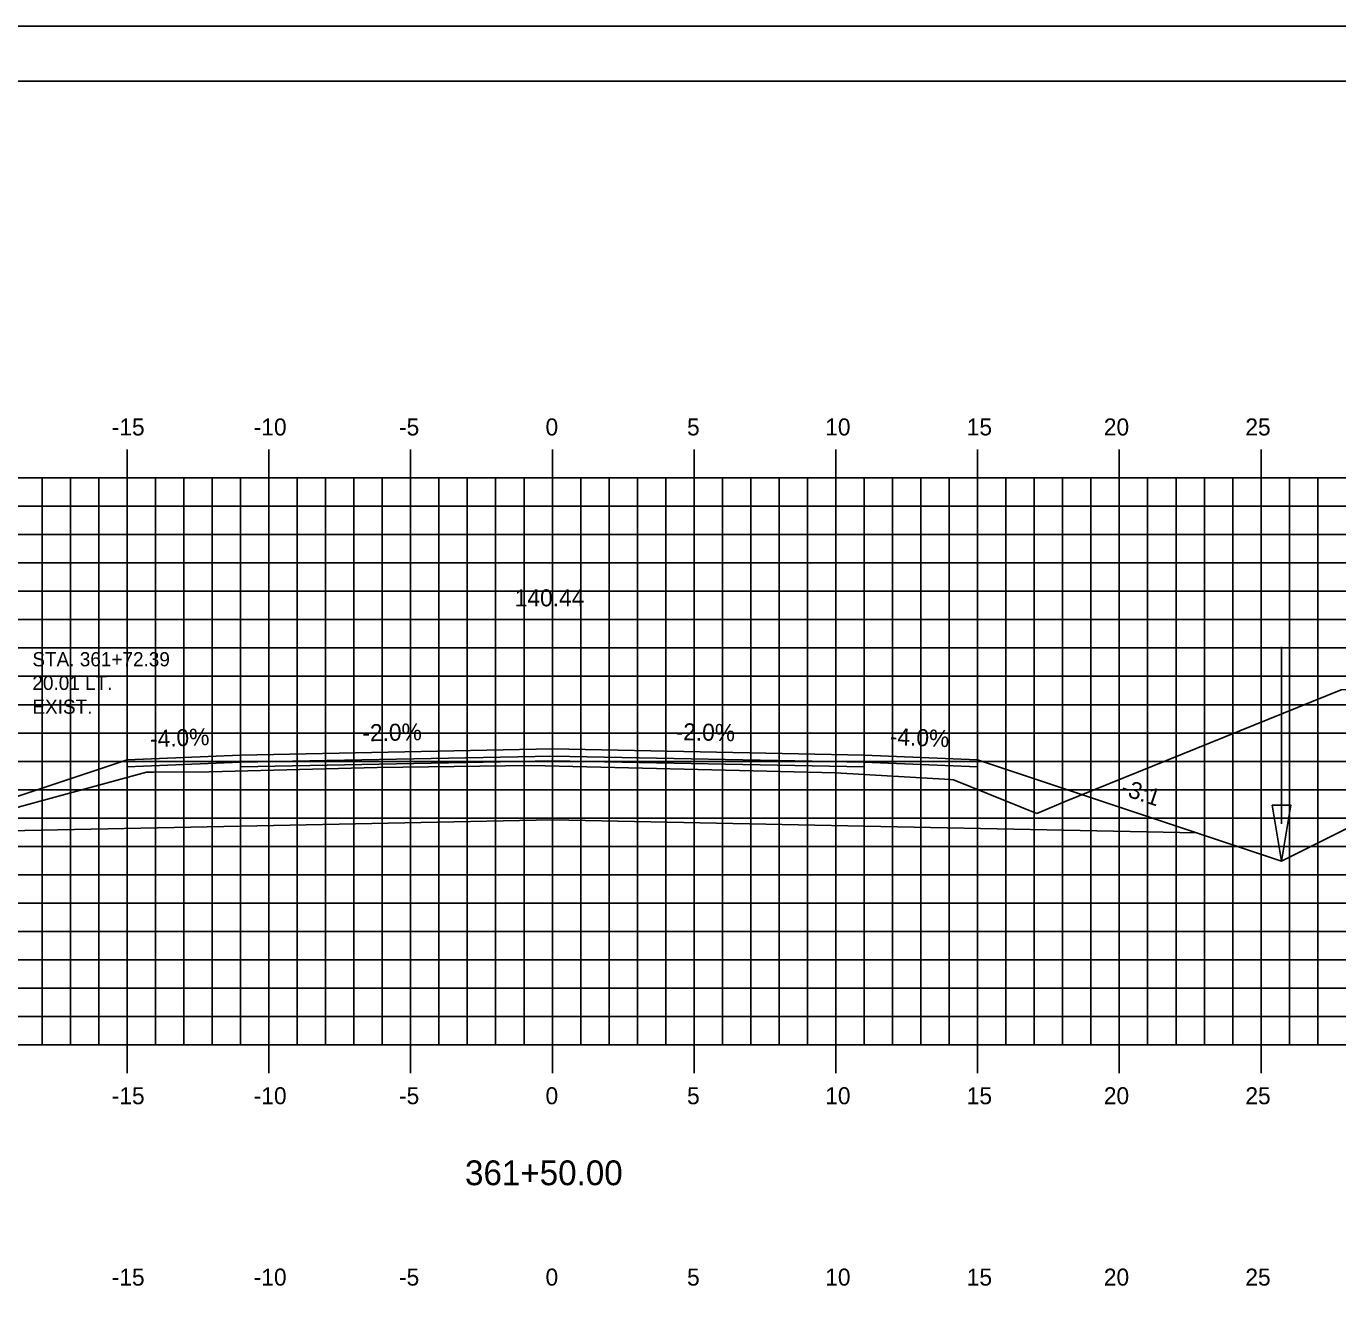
# Model space of a CAD drawing. Extents: x 1146525 to 1146695, y 608981 to 609091.
# Drawn here: x 1146589.11 to 1146635.38, y 609046.58 to 609091.28 of the extents above; entities that cross this region are included whole.
import ezdxf

# ---------------------------------------------------------------- set-up
doc = ezdxf.new("R2010")
doc.units = 0
for name, color, linetype in [('ANNOTATION', 7, 'Continuous'), ('BORDER', 7, 'Continuous'), ('D_Drainage_Ditch_Line', 7, 'Continuous'), ('D_Roadway_Centerline', 7, 'Continuous'), ('D_Roadway_Centerline_Text', 7, 'Continuous'), ('D_Roadway_Edge_Shoulder', 7, 'Continuous'), ('D_Roadway_Edge_TW', 7, 'Continuous'), ('D_Roadway_Pavement', 7, 'Continuous'), ('D_Roadway_SlopeLines', 7, 'Continuous'), ('D_Roadway_SubGrade', 7, 'Continuous'), ('D_Text_Monospaced', 7, 'Continuous'), ('H_V ANNOTATION', 7, 'Continuous'), ('MAJOR', 7, 'Continuous'), ('MINOR', 7, 'Continuous'), ('PLOT BOUNDARY', 7, 'Continuous'), ('S_Roadway_Centerline', 7, 'Continuous')]:
    doc.layers.add(name, color=color, linetype=linetype)

msp = doc.modelspace()

# ---------------------------------------------------------------- linework, layer by layer
msp.add_lwpolyline([(1146572.045, 609065.661), (1146573.295, 609065.521), (1146574.545, 609065.242), (1146575.795, 609064.824), (1146577.045, 609064.269), (1146581.947, 609061.818), (1146584.947, 609062.818), (1146592.67, 609065.392), (1146592.671, 609065.392), (1146596.671, 609065.552), (1146607.671, 609065.772), (1146618.671, 609065.552), (1146622.671, 609065.392), (1146630.395, 609062.818), (1146633.395, 609061.818), (1146643.18, 609066.71), (1146644.43, 609067.259), (1146645.68, 609067.654), (1146646.93, 609067.897), (1146648.18, 609067.986)])
at = {"layer": 'BORDER'}
msp.add_lwpolyline([(1146532.671, 608984.335), (1146692.671, 608984.335), (1146692.671, 609089.335), (1146532.671, 609089.335)], close=True, dxfattribs=at)
at = {"layer": 'D_Drainage_Ditch_Line'}
msp.add_line((1146633.395, 609063.13), (1146633.395, 609069.374), dxfattribs=at)
msp.add_lwpolyline([(1146633.067, 609063.786), (1146633.723, 609063.786), (1146633.395, 609061.818)], close=True, dxfattribs=at)
at = {"layer": 'D_Roadway_Edge_Shoulder'}
for points in [[(1146596.671, 609065.552), (1146592.671, 609065.392), (1146592.671, 609065.142), (1146596.671, 609065.302)], [(1146618.671, 609065.552), (1146622.671, 609065.392), (1146622.671, 609065.142), (1146618.671, 609065.302)]]:
    msp.add_lwpolyline(points, close=True, dxfattribs=at)
at = {"layer": 'D_Roadway_Edge_TW'}
msp.add_lwpolyline([(1146596.671, 609065.302), (1146596.671, 609065.552), (1146607.671, 609065.772), (1146618.671, 609065.552), (1146618.671, 609065.302), (1146607.671, 609065.522)], close=True, dxfattribs=at)
at = {"layer": 'D_Roadway_Pavement'}
msp.add_lwpolyline([(1146596.671, 609065.136), (1146596.671, 609065.302), (1146607.671, 609065.522), (1146618.671, 609065.302), (1146618.671, 609065.136), (1146607.671, 609065.356)], close=True, dxfattribs=at)
at = {"layer": 'D_Roadway_SlopeLines'}
for points in [[(1146633.395, 609061.818), (1146643.18, 609066.71), (1146644.43, 609067.259), (1146645.68, 609067.654), (1146646.93, 609067.897), (1146648.18, 609067.986)], [(1146630.395, 609062.818), (1146633.395, 609061.818)]]:
    msp.add_lwpolyline(points, dxfattribs=at)
at = {"layer": 'D_Roadway_SubGrade'}
for points in [[(1146596.671, 609065.136), (1146596.671, 609065.302), (1146592.671, 609065.142), (1146592.671, 609065.392), (1146592.67, 609065.392), (1146584.947, 609062.818), (1146596.671, 609063.052)], [(1146596.671, 609063.052), (1146596.671, 609065.136), (1146607.671, 609065.356), (1146618.671, 609065.136), (1146618.671, 609063.052), (1146607.671, 609063.272)], [(1146618.671, 609065.136), (1146618.671, 609065.302), (1146622.671, 609065.142), (1146622.671, 609065.392), (1146622.671, 609065.392), (1146630.395, 609062.818), (1146618.671, 609063.052)]]:
    msp.add_lwpolyline(points, close=True, dxfattribs=at)
at = {"layer": 'MAJOR'}
for p, q in [((1146592.671, 609076.337), (1146592.671, 609075.335)), ((1146597.671, 609076.337), (1146597.671, 609075.335)), ((1146602.671, 609076.337), (1146602.671, 609075.335)), ((1146607.671, 609076.337), (1146607.671, 609075.335)), ((1146612.671, 609076.337), (1146612.671, 609075.335)), ((1146617.671, 609076.337), (1146617.671, 609075.335)), ((1146622.671, 609076.337), (1146622.671, 609075.335)), ((1146627.671, 609076.337), (1146627.671, 609075.335)), ((1146632.671, 609076.337), (1146632.671, 609075.335)), ((1146537.671, 609075.335), (1146677.671, 609075.335)), ((1146537.671, 609075.335), (1146677.671, 609075.335)), ((1146592.671, 609055.335), (1146592.671, 609075.335)), ((1146597.671, 609055.335), (1146597.671, 609075.335)), ((1146602.671, 609055.335), (1146602.671, 609075.335)), ((1146607.671, 609055.335), (1146607.671, 609075.335)), ((1146612.671, 609055.335), (1146612.671, 609075.335)), ((1146617.671, 609055.335), (1146617.671, 609075.335)), ((1146622.671, 609055.335), (1146622.671, 609075.335)), ((1146627.671, 609055.335), (1146627.671, 609075.335)), ((1146632.671, 609055.335), (1146632.671, 609075.335)), ((1146537.671, 609070.335), (1146677.671, 609070.335)), ((1146537.671, 609065.335), (1146677.671, 609065.335)), ((1146537.671, 609060.335), (1146677.671, 609060.335)), ((1146537.671, 609055.335), (1146677.671, 609055.335)), ((1146537.671, 609055.335), (1146677.671, 609055.335)), ((1146592.671, 609054.333), (1146592.671, 609055.335)), ((1146597.671, 609054.333), (1146597.671, 609055.335)), ((1146602.671, 609054.333), (1146602.671, 609055.335)), ((1146607.671, 609054.333), (1146607.671, 609055.335)), ((1146612.671, 609054.333), (1146612.671, 609055.335)), ((1146617.671, 609054.333), (1146617.671, 609055.335)), ((1146622.671, 609054.333), (1146622.671, 609055.335)), ((1146627.671, 609054.333), (1146627.671, 609055.335)), ((1146632.671, 609054.333), (1146632.671, 609055.335))]:
    msp.add_line(p, q, dxfattribs=at)
at = {"layer": 'MINOR'}
for p, q in [((1146589.671, 609055.335), (1146589.671, 609075.335)), ((1146590.671, 609055.335), (1146590.671, 609075.335)), ((1146591.671, 609055.335), (1146591.671, 609075.335)), ((1146593.671, 609055.335), (1146593.671, 609075.335)), ((1146594.671, 609055.335), (1146594.671, 609075.335)), ((1146595.671, 609055.335), (1146595.671, 609075.335)), ((1146596.671, 609055.335), (1146596.671, 609075.335)), ((1146598.671, 609055.335), (1146598.671, 609075.335)), ((1146599.671, 609055.335), (1146599.671, 609075.335)), ((1146600.671, 609055.335), (1146600.671, 609075.335)), ((1146601.671, 609055.335), (1146601.671, 609075.335)), ((1146603.671, 609055.335), (1146603.671, 609075.335)), ((1146604.671, 609055.335), (1146604.671, 609075.335)), ((1146605.671, 609055.335), (1146605.671, 609075.335)), ((1146606.671, 609055.335), (1146606.671, 609075.335)), ((1146608.671, 609055.335), (1146608.671, 609075.335)), ((1146609.671, 609055.335), (1146609.671, 609075.335)), ((1146610.671, 609055.335), (1146610.671, 609075.335)), ((1146611.671, 609055.335), (1146611.671, 609075.335)), ((1146613.671, 609055.335), (1146613.671, 609075.335)), ((1146614.671, 609055.335), (1146614.671, 609075.335)), ((1146615.671, 609055.335), (1146615.671, 609075.335)), ((1146616.671, 609055.335), (1146616.671, 609075.335)), ((1146618.671, 609055.335), (1146618.671, 609075.335)), ((1146619.671, 609055.335), (1146619.671, 609075.335)), ((1146620.671, 609055.335), (1146620.671, 609075.335)), ((1146621.671, 609055.335), (1146621.671, 609075.335)), ((1146623.671, 609055.335), (1146623.671, 609075.335)), ((1146624.671, 609055.335), (1146624.671, 609075.335)), ((1146625.671, 609055.335), (1146625.671, 609075.335)), ((1146626.671, 609055.335), (1146626.671, 609075.335)), ((1146628.671, 609055.335), (1146628.671, 609075.335)), ((1146629.671, 609055.335), (1146629.671, 609075.335)), ((1146630.671, 609055.335), (1146630.671, 609075.335)), ((1146631.671, 609055.335), (1146631.671, 609075.335)), ((1146633.671, 609055.335), (1146633.671, 609075.335)), ((1146634.671, 609055.335), (1146634.671, 609075.335)), ((1146537.671, 609074.335), (1146677.671, 609074.335)), ((1146537.671, 609073.335), (1146677.671, 609073.335)), ((1146537.671, 609072.335), (1146677.671, 609072.335)), ((1146537.671, 609071.335), (1146677.671, 609071.335)), ((1146537.671, 609069.335), (1146677.671, 609069.335)), ((1146537.671, 609068.335), (1146677.671, 609068.335)), ((1146537.671, 609067.335), (1146677.671, 609067.335)), ((1146537.671, 609066.335), (1146677.671, 609066.335)), ((1146537.671, 609064.335), (1146677.671, 609064.335)), ((1146537.671, 609063.335), (1146677.671, 609063.335)), ((1146537.671, 609062.335), (1146677.671, 609062.335)), ((1146537.671, 609061.335), (1146677.671, 609061.335)), ((1146537.671, 609059.335), (1146677.671, 609059.335)), ((1146537.671, 609058.335), (1146677.671, 609058.335)), ((1146537.671, 609057.335), (1146677.671, 609057.335)), ((1146537.671, 609056.335), (1146677.671, 609056.335))]:
    msp.add_line(p, q, dxfattribs=at)
at = {"layer": 'PLOT BOUNDARY'}
msp.add_lwpolyline([(1146524.578, 608981.276), (1146694.578, 608981.276), (1146694.578, 609091.276), (1146524.578, 609091.276)], close=True, dxfattribs=at)
at = {"layer": 'S_Roadway_Centerline'}
msp.add_lwpolyline([(1146555.658, 609066.541), (1146562.215, 609066.221), (1146582.411, 609065.07), (1146583.316, 609064.912), (1146587.853, 609063.497), (1146588.571, 609063.642), (1146593.356, 609064.948), (1146593.601, 609064.956), (1146595.56, 609064.969), (1146601.488, 609065.115), (1146606.926, 609065.194), (1146612.815, 609065.044), (1146617.656, 609064.926), (1146621.703, 609064.693), (1146621.82, 609064.681), (1146621.879, 609064.655), (1146624.765, 609063.492), (1146625.761, 609063.915), (1146635.495, 609067.854), (1146654.514, 609068.052), (1146655.612, 609068.025)], dxfattribs=at)

# ---------------------------------------------------------------- texts
at = {"layer": 'ANNOTATION'}
for s, rotation, p in [('-2.0%', 1.1458, (1146600.974, 609066.039)), ('-2.0%', 358.8542, (1146612.014, 609066.086)), ('-4.0%', 2.2906, (1146593.487, 609065.826)), ('-4.0%', 357.7094, (1146619.567, 609065.917)), ('-3:1', 341.5652, (1146627.683, 609064.176))]:
    msp.add_text(s, height=0.6, rotation=rotation, dxfattribs=at).set_placement(p)
at = {"layer": 'D_Roadway_Centerline'}
for s, p in [('C', (1146607.666, 609065.772)), ('L', (1146607.671, 609065.765))]:
    msp.add_text(s, height=0.0146, dxfattribs=at).set_placement(p)
at = {"layer": 'D_Roadway_Centerline_Text'}
msp.add_text('140.44', height=0.6, dxfattribs=at).set_placement((1146606.344, 609070.804))
at = {"layer": 'D_Text_Monospaced'}
for s, height, p in [('STA. 361+72.39', 0.49998, (1146589.328, 609068.688)), ('20.01 LT.', 0.5, (1146589.328, 609067.854)), ('EXIST. ', 0.5, (1146589.328, 609067.014))]:
    msp.add_text(s, height=height, dxfattribs=at).set_placement(p)
at = {"layer": 'H_V ANNOTATION'}
for s, height, p in [('-15', 0.6, (1146592.128, 609076.835)), ('-10', 0.6, (1146597.136, 609076.835)), ('-5', 0.6, (1146602.262, 609076.835)), ('0', 0.6, (1146607.43, 609076.835)), ('5', 0.6, (1146612.422, 609076.835)), ('10', 0.6, (1146617.297, 609076.835)), ('15', 0.6, (1146622.289, 609076.835)), ('20', 0.6, (1146627.125, 609076.835)), ('25', 0.6, (1146632.117, 609076.835)), ('-15', 0.6, (1146592.128, 609053.235)), ('-10', 0.6, (1146597.136, 609053.235)), ('-5', 0.6, (1146602.262, 609053.235)), ('0', 0.6, (1146607.43, 609053.235)), ('5', 0.6, (1146612.422, 609053.235)), ('10', 0.6, (1146617.297, 609053.235)), ('15', 0.6, (1146622.289, 609053.235)), ('20', 0.6, (1146627.125, 609053.235)), ('25', 0.6, (1146632.117, 609053.235)), ('361+50.00', 0.875, (1146604.589, 609050.378)), ('-15', 0.6, (1146592.128, 609046.835)), ('-10', 0.6, (1146597.136, 609046.835)), ('-5', 0.6, (1146602.262, 609046.835)), ('0', 0.6, (1146607.43, 609046.835)), ('5', 0.6, (1146612.422, 609046.835)), ('10', 0.6, (1146617.297, 609046.835)), ('15', 0.6, (1146622.289, 609046.835)), ('20', 0.6, (1146627.125, 609046.835)), ('25', 0.6, (1146632.117, 609046.835))]:
    msp.add_text(s, height=height, dxfattribs=at).set_placement(p)
at = {"layer": 'S_Roadway_Centerline'}
for s, p in [('L', (1146606.918, 609065.186)), ('C', (1146606.921, 609065.194))]:
    msp.add_text(s, height=0.0146, dxfattribs=at).set_placement(p)

doc.saveas('drawing.dxf')
